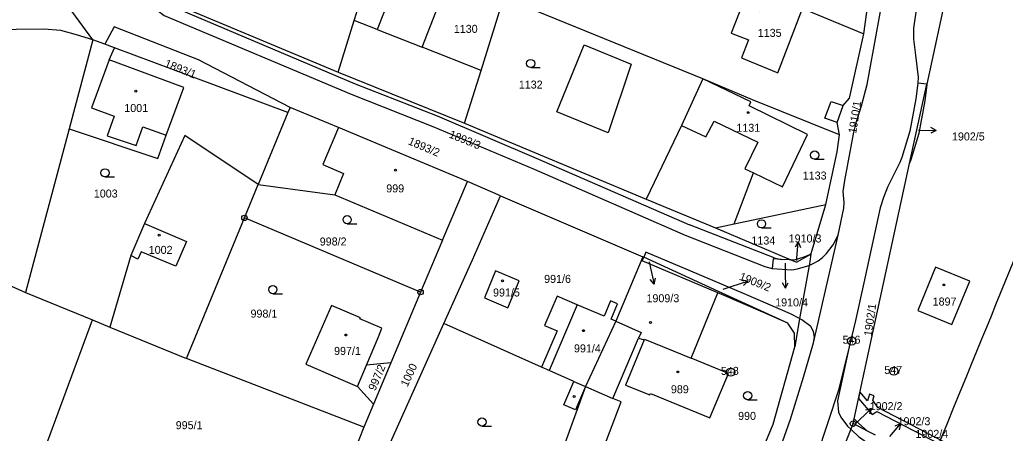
# Model space of a CAD drawing. Extents: x -587171 to -555306, y -1167727 to -1074732.
# Drawn here: x -560044.2 to -559864.5, y -1077385.1 to -1077309.7 of the extents above; entities that cross this region are included whole.
import ezdxf

# ---------------------------------------------------------------- set-up
doc = ezdxf.new("R2010")
doc.units = 0
for name, color, linetype in [('Hranice parcel', 7, 'Continuous'), ('Parcelní čísla', 7, 'Continuous'), ('Pop  PČ popisy', 7, 'Continuous'), ('Poz předměty', 7, 'Continuous'), ('Vnitřní kresba', 7, 'Continuous'), ('Věcná břemena k části', 7, 'Continuous'), ('Značky bodu BP', 7, 'Continuous'), ('Značky budov', 7, 'Continuous'), ('Značky kultur', 7, 'Continuous')]:
    doc.layers.add(name, color=color, linetype=linetype)

msp = doc.modelspace()

# ---------------------------------------------------------------- linework, layer by layer
at = {"layer": 'Hranice parcel'}
for p, q in [((-559983.17, -1077309.84), (-559978.88, -1077295.93)), ((-559890.24, -1077312.26), (-559889.22, -1077304.66)), ((-559875.1, -1077304.36), (-559878.81, -1077321.46)), ((-560030.81, -1077313.36), (-560036.87, -1077305.12)), ((-560016.82, -1077306.44), (-559986.08, -1077319.26)), ((-559960.06, -1077318.93), (-559955.87, -1077305.57)), ((-559919.63, -1077320.49), (-559953.55, -1077306.68)), ((-559986.08, -1077319.26), (-559983.17, -1077309.84)), ((-560030.81, -1077313.36), (-560035.15, -1077329.59)), ((-560028.64, -1077314.17), (-560030.81, -1077313.36)), ((-560026.89, -1077314.82), (-560028.64, -1077314.17)), ((-559963.08, -1077328.55), (-559960.06, -1077318.93)), ((-559986.08, -1077319.26), (-559963.08, -1077328.55)), ((-559881.94, -1077335.91), (-559878.81, -1077321.46)), ((-559994.88, -1077325.68), (-559995.29, -1077326.62)), ((-559995.29, -1077326.62), (-560000.68, -1077339.72)), ((-560035.15, -1077329.59), (-560043.13, -1077359.42)), ((-559963.08, -1077328.55), (-559929.98, -1077342.38)), ((-559892.03, -1077382.43), (-559881.94, -1077335.91)), ((-560003.19, -1077345.82), (-560000.68, -1077339.72)), ((-559967.11, -1077349.89), (-559962.53, -1077339.19)), ((-559956.53, -1077341.81), (-559962.53, -1077339.19)), ((-559956.53, -1077341.81), (-559930.55, -1077352.91)), ((-559929.98, -1077342.38), (-559917.34, -1077347.66)), ((-559913.91, -1077346.93), (-559897.19, -1077343.37)), ((-559899.86, -1077352.3), (-559897.19, -1077343.37)), ((-560013.73, -1077371.45), (-560003.19, -1077345.82)), ((-559971.08, -1077359.35), (-560003.19, -1077345.82)), ((-559917.34, -1077347.66), (-559913.91, -1077346.93)), ((-559917.34, -1077347.66), (-559903.58, -1077353.47)), ((-560062.31, -1077350.83), (-560043.13, -1077359.42)), ((-559967.11, -1077349.89), (-559971.08, -1077359.35)), ((-559930.55, -1077352.91), (-559935.49, -1077364.62)), ((-559930.38, -1077352.99), (-559930.55, -1077352.91)), ((-559899.9, -1077352.45), (-559899.86, -1077352.3)), ((-560043.13, -1077359.42), (-560030.92, -1077364.43)), ((-559971.08, -1077359.35), (-559976.49, -1077372.24)), ((-560030.92, -1077364.43), (-560027.75, -1077365.72)), ((-560027.75, -1077365.72), (-560013.73, -1077371.45)), ((-559978.26, -1077390.49), (-559966.82, -1077365.06)), ((-559949.05, -1077373.02), (-559966.82, -1077365.06)), ((-559935.49, -1077364.62), (-559940.99, -1077376.58)), ((-559901.97, -1077364.19), (-559902.87, -1077369.32)), ((-559981.41, -1077383.96), (-560013.73, -1077371.45)), ((-559982.56, -1077376.53), (-559980.95, -1077372.68)), ((-559976.49, -1077372.24), (-559980.95, -1077372.68)), ((-559976.49, -1077372.24), (-559979.66, -1077379.8)), ((-559982.56, -1077376.53), (-559979.66, -1077379.8)), ((-559940.99, -1077376.58), (-559945, -1077387.63)), ((-559979.66, -1077379.8), (-559981.41, -1077383.96)), ((-559892.23, -1077383.33), (-559892.63, -1077384.34)), ((-559892.23, -1077383.33), (-559892.03, -1077382.43)), ((-559889.58, -1077384.72), (-559892.23, -1077383.33)), ((-559892.63, -1077384.34), (-559894.93, -1077390.1)), ((-559888.16, -1077385.46), (-559889.58, -1077384.72))]:
    msp.add_line(p, q, dxfattribs=at)
for points in [[(-559929.49, -1077288.89), (-559929.57, -1077289.19), (-559932.51, -1077296.57), (-559925.45, -1077299.01), (-559908.07, -1077305.03), (-559909.31, -1077308.22), (-559912.46, -1077307.06), (-559914.44, -1077312.13), (-559911.3, -1077313.35), (-559912.58, -1077316.63), (-559905.97, -1077319.36), (-559901.46, -1077307.62), (-559890.24, -1077312.26)], [(-559900.26, -1077354.47), (-559899.5, -1077354.14), (-559898.62, -1077353.63), (-559897.81, -1077353.03), (-559897.09, -1077352.34), (-559895.86, -1077350.73), (-559894.96, -1077348.94), (-559893.9, -1077344.02), (-559893.86, -1077343.01), (-559894.02, -1077341), (-559893.76, -1077339.02), (-559892.08, -1077330.19), (-559891.58, -1077328.25), (-559890.72, -1077325.37), (-559889.66, -1077321.48), (-559885.92, -1077300.78), (-559885.95, -1077299.24), (-559886.26, -1077298.26), (-559886.87, -1077296.86), (-559887.03, -1077296.56)], [(-559960.06, -1077318.93), (-559970.81, -1077314.7), (-559966.79, -1077304.34), (-559974.94, -1077301.15), (-559979, -1077311.48), (-559983.17, -1077309.84)], [(-560019.97, -1077306.15), (-560019.65, -1077307.12), (-560019.09, -1077307.96), (-560017.85, -1077308.9), (-559983.72, -1077323.25), (-559968.84, -1077329.13), (-559950.38, -1077336.96), (-559922.87, -1077348.95), (-559908.29, -1077354.69), (-559906.95, -1077355.04)], [(-560030.81, -1077313.36), (-560033.78, -1077312.44), (-560036.69, -1077311.68), (-560039.79, -1077311.41), (-560054.98, -1077311.59), (-560063.88, -1077312.39), (-560075.71, -1077315.12), (-560089.9, -1077319.46), (-560101.1, -1077323.43), (-560106.22, -1077325.48)], [(-559994.88, -1077325.68), (-560011.55, -1077317.03), (-560026.95, -1077310.97), (-560028.64, -1077314.17)], [(-559894.71, -1077330.66), (-559895.15, -1077328.43), (-559897.37, -1077327.64), (-559896.22, -1077324.58), (-559894.05, -1077325.32), (-559892.91, -1077324.01), (-559890.24, -1077312.26)], [(-560035.15, -1077329.59), (-560019.01, -1077334.99), (-560017.48, -1077330.74), (-560014.22, -1077322.02), (-560027.88, -1077316.99), (-560026.89, -1077314.82)], [(-559995.29, -1077326.62), (-560012.52, -1077320.18), (-560026.89, -1077314.82)], [(-559919.63, -1077320.49), (-559923.5, -1077328.97), (-559929.98, -1077342.38)], [(-559913.91, -1077346.93), (-559910.4, -1077337.62), (-559905.12, -1077340.17), (-559900.54, -1077330.62), (-559911.16, -1077325.4), (-559910.86, -1077324.65), (-559919.63, -1077320.49)], [(-559894.71, -1077330.66), (-559910.59, -1077324.3), (-559919.63, -1077320.49)], [(-559878.81, -1077321.46), (-559880.41, -1077321.24), (-559880.81, -1077324.13), (-559881.87, -1077330.03), (-559883.35, -1077334.81), (-559883.72, -1077335.71), (-559885.98, -1077340.19), (-559886.66, -1077342.07), (-559887.27, -1077343.97), (-559887.72, -1077345.91), (-559890.29, -1077357.68), (-559891.79, -1077364.53), (-559892.97, -1077369.35), (-559895.09, -1077379.19), (-559894.88, -1077381.21), (-559894.49, -1077382.17), (-559893.24, -1077383.78), (-559892.63, -1077384.34)], [(-559881.94, -1077335.91), (-559881.62, -1077335.17), (-559880.15, -1077330.37), (-559879.08, -1077324.46), (-559878.69, -1077321.48), (-559878.81, -1077321.46)], [(-559962.53, -1077339.19), (-559986.03, -1077329.34), (-559994.88, -1077325.68)], [(-560000.68, -1077339.72), (-560014.03, -1077330.81), (-560021.39, -1077346.86), (-560023.92, -1077352.7), (-560027.75, -1077365.72)], [(-559897.19, -1077343.37), (-559895.13, -1077333.76), (-559894.71, -1077330.66)], [(-560000.68, -1077339.72), (-559986.71, -1077341.63), (-559967.11, -1077349.89)], [(-559966.82, -1077365.06), (-559961.61, -1077353.47), (-559956.53, -1077341.81)], [(-559916.86, -1077359.51), (-559930.65, -1077353.66), (-559930.38, -1077352.99)], [(-559901.97, -1077364.19), (-559903.62, -1077363.31), (-559911.75, -1077359.79), (-559922.24, -1077355.32), (-559930, -1077352.07), (-559930.38, -1077352.99)], [(-559904.13, -1077365.04), (-559916.75, -1077359.25), (-559930.38, -1077352.99)], [(-559903.58, -1077353.47), (-559903.79, -1077353.49), (-559905.36, -1077353.4), (-559906.77, -1077353.31), (-559906.95, -1077355.04)], [(-559903.58, -1077353.47), (-559902.75, -1077353.41), (-559901.13, -1077352.94), (-559900.13, -1077352.48), (-559899.86, -1077352.3)], [(-559903.58, -1077353.47), (-559902.55, -1077353.91), (-559899.9, -1077352.45)], [(-559899.9, -1077352.45), (-559900.13, -1077353.75), (-559900.26, -1077354.47)], [(-559906.95, -1077355.04), (-559903.38, -1077355.27), (-559902.39, -1077355.13), (-559900.45, -1077354.55), (-559900.26, -1077354.47)], [(-559900.26, -1077354.47), (-559901.91, -1077363.84), (-559901.97, -1077364.19)], [(-559880.42, -1077362.71), (-559874.2, -1077365.28), (-559870.95, -1077357.34), (-559877.18, -1077354.78), (-559880.42, -1077362.71)], [(-559957.42, -1077355.46), (-559959.4, -1077360.41), (-559955.16, -1077362.19), (-559953.13, -1077357.3), (-559957.42, -1077355.46)], [(-559935.49, -1077364.62), (-559936.33, -1077364.29), (-559935.17, -1077361.46), (-559936.44, -1077360.95), (-559937.62, -1077363.73), (-559942.51, -1077361.67), (-559946.2, -1077360.09), (-559948.5, -1077365.42), (-559946.16, -1077366.39), (-559949.05, -1077373.02)], [(-559938.79, -1077390.54), (-559934.48, -1077379.33), (-559936.02, -1077378.76), (-559931.32, -1077367.72), (-559930.32, -1077368.08), (-559933.69, -1077376.29), (-559929.26, -1077378.1), (-559929.16, -1077377.85), (-559918.33, -1077382.29), (-559914.91, -1077374.17), (-559921.77, -1077371.37), (-559916.86, -1077359.51)], [(-559904.13, -1077365.04), (-559908.67, -1077362.99), (-559916.18, -1077359.8), (-559916.86, -1077359.51)], [(-559980.95, -1077372.68), (-559978.78, -1077367.5), (-559978.15, -1077365.93), (-559982.13, -1077364.22), (-559982.05, -1077364.03), (-559987.3, -1077361.8), (-559991.97, -1077372.48), (-559982.56, -1077376.53)], [(-560031.56, -1077394.23), (-560040.52, -1077390.39), (-560030.92, -1077364.43)], [(-559905.44, -1077387.67), (-559903.62, -1077382.49), (-559901.27, -1077374.84), (-559899.42, -1077368.57), (-559899.24, -1077367.56), (-559899.43, -1077366.53), (-559899.95, -1077365.64), (-559901.59, -1077364.39), (-559901.97, -1077364.19)], [(-559902.87, -1077369.32), (-559902.91, -1077366.86), (-559904.13, -1077365.04)], [(-559915.17, -1077401.61), (-559908.11, -1077386.67), (-559906.8, -1077383.45), (-559902.87, -1077369.32)], [(-559940.99, -1077376.58), (-559942.83, -1077380.79), (-559944.97, -1077379.88), (-559943.15, -1077375.63), (-559947.66, -1077373.64), (-559949.05, -1077373.02)], [(-559889.58, -1077384.72), (-559891.2, -1077383.33), (-559892.03, -1077382.43)], [(-559981.41, -1077383.96), (-559985.09, -1077393.19), (-559990.04, -1077404.64)], [(-559881.9, -1077390.3), (-559890.22, -1077386.44), (-559891.04, -1077385.83), (-559892.63, -1077384.34)]]:
    msp.add_lwpolyline(points, dxfattribs=at)
at = {"layer": 'Pop  PČ popisy'}
for p, q in [((-559880.33, -1077329.8), (-559880.06, -1077329.81)), ((-559880.06, -1077329.81), (-559877.06, -1077329.86)), ((-559877.06, -1077329.86), (-559878.07, -1077330.35)), ((-559877.06, -1077329.86), (-559878.05, -1077329.34)), ((-559902.22, -1077350.19), (-559902.81, -1077351.14)), ((-559902.48, -1077353.18), (-559902.22, -1077350.19)), ((-559902.22, -1077350.19), (-559901.81, -1077351.23)), ((-559902.51, -1077353.6), (-559902.48, -1077353.18)), ((-559929.41, -1077353.86), (-559929.16, -1077354.99)), ((-559929.16, -1077354.99), (-559928.48, -1077357.91)), ((-559904.63, -1077354.08), (-559904.6, -1077355.65)), ((-559928.48, -1077357.91), (-559928.22, -1077356.83)), ((-559904.6, -1077355.65), (-559904.55, -1077358.65)), ((-559928.48, -1077357.91), (-559929.2, -1077357.05)), ((-559915.9, -1077358.82), (-559914.25, -1077358.28)), ((-559914.25, -1077358.28), (-559911.4, -1077357.35)), ((-559911.4, -1077357.35), (-559912.5, -1077357.19)), ((-559911.4, -1077357.35), (-559912.19, -1077358.14)), ((-559904.55, -1077358.65), (-559905.07, -1077357.66)), ((-559904.55, -1077358.65), (-559904.06, -1077357.64)), ((-559891.05, -1077382.64), (-559888.89, -1077380.55)), ((-559888.89, -1077380.55), (-559889.96, -1077380.89)), ((-559888.89, -1077380.55), (-559889.26, -1077381.61)), ((-559891.76, -1077383.33), (-559891.05, -1077382.64)), ((-559885.5, -1077385.66), (-559883.57, -1077383.36)), ((-559883.57, -1077383.36), (-559884.6, -1077383.81)), ((-559883.57, -1077383.36), (-559883.83, -1077384.45))]:
    msp.add_line(p, q, dxfattribs=at)
at = {"layer": 'Poz předměty'}
msp.add_line((-559845.74, -1077311.35), (-559865.41, -1077359.61), dxfattribs=at)
msp.add_lwpolyline([(-559865.41, -1077359.61), (-559866.24, -1077361.64), (-559867.08, -1077363.71), (-559867.93, -1077365.8), (-559868.81, -1077367.95), (-559869.73, -1077370.2), (-559870.69, -1077372.54), (-559871.69, -1077374.99), (-559872.76, -1077377.62), (-559873.89, -1077380.39), (-559875.09, -1077383.33), (-559876.4, -1077386.52)], dxfattribs=at)
at = {"layer": 'Vnitřní kresba'}
for p, q in [((-560016.75, -1077307.12), (-559983, -1077321.36)), ((-559979, -1077311.48), (-559970.81, -1077314.7)), ((-559946.24, -1077326.5), (-559941.26, -1077314.28)), ((-559941.26, -1077314.28), (-559932.67, -1077317.79)), ((-560027.88, -1077316.99), (-560031.1, -1077325.74)), ((-559932.67, -1077317.79), (-559936.89, -1077330.3)), ((-559880.39, -1077320.16), (-559880.41, -1077321.24)), ((-559983, -1077321.36), (-559968.06, -1077327.24)), ((-560031.1, -1077325.74), (-560026.95, -1077327.27)), ((-559895.15, -1077328.43), (-559894.05, -1077325.32)), ((-560026.95, -1077327.27), (-560028.23, -1077330.85)), ((-559968.06, -1077327.24), (-559949.59, -1077335.09)), ((-559936.89, -1077330.3), (-559946.24, -1077326.5)), ((-559919.06, -1077331.06), (-559917.58, -1077328.17)), ((-559917.58, -1077328.17), (-559909.58, -1077332.03)), ((-560022.94, -1077332.61), (-560021.7, -1077329.19)), ((-560021.7, -1077329.19), (-560017.48, -1077330.74)), ((-559986.03, -1077329.34), (-559988.89, -1077336.1)), ((-559923.5, -1077328.97), (-559919.06, -1077331.06)), ((-560028.23, -1077330.85), (-560022.94, -1077332.61)), ((-559909.58, -1077332.03), (-559911.94, -1077336.89)), ((-559949.59, -1077335.09), (-559922.08, -1077347.06)), ((-559988.89, -1077336.1), (-559985.11, -1077337.7)), ((-559911.94, -1077336.89), (-559910.4, -1077337.62)), ((-559985.11, -1077337.7), (-559986.71, -1077341.63)), ((-560021.39, -1077346.86), (-560013.77, -1077350.11)), ((-559906.59, -1077353.11), (-559922.08, -1077347.06)), ((-559899.42, -1077368.57), (-559894.96, -1077348.94)), ((-560013.77, -1077350.11), (-560015.68, -1077354.61)), ((-560022.61, -1077353.32), (-560023.92, -1077352.7)), ((-560021.99, -1077352.01), (-560022.61, -1077353.32)), ((-560015.68, -1077354.61), (-560021.99, -1077352.01)), ((-559906.59, -1077353.11), (-559905.36, -1077353.4)), ((-559942.51, -1077361.67), (-559947.66, -1077373.64)), ((-559935.49, -1077364.62), (-559930.89, -1077366.72)), ((-559930.89, -1077366.72), (-559931.32, -1077367.72)), ((-559930.32, -1077368.08), (-559930.25, -1077367.91)), ((-559930.25, -1077367.91), (-559921.77, -1077371.37)), ((-559892.97, -1077369.35), (-559894.9, -1077377.22)), ((-559943.15, -1077375.63), (-559940.99, -1077376.58)), ((-559940.99, -1077376.58), (-559936.02, -1077378.76)), ((-559894.9, -1077377.22), (-559899.37, -1077390.82))]:
    msp.add_line(p, q, dxfattribs=at)
msp.add_lwpolyline([(-559880.52, -1077306.69), (-559881.2, -1077311.2), (-559881.19, -1077313.22), (-559880.84, -1077316.18), (-559880.39, -1077320.16)], dxfattribs=at)
at = {"layer": 'Věcná břemena k části'}
msp.add_lwpolyline([(-559859.52, -1077396.96), (-559855.23, -1077398.97), (-559856.09, -1077398.29), (-559860.3, -1077395.64), (-559866.99, -1077392.11), (-559869.5, -1077390.07), (-559871.22, -1077389.29), (-559872.65, -1077388.25), (-559887.7, -1077380.39), (-559888.62, -1077379.05), (-559888.38, -1077378.28), (-559889.22, -1077377.97), (-559889.59, -1077379.15), (-559890.97, -1077377.54), (-559891.24, -1077378.77), (-559888.75, -1077381.66), (-559887.87, -1077381.09), (-559873.01, -1077388.85), (-559871.58, -1077389.89), (-559869.88, -1077390.67), (-559867.37, -1077392.69), (-559860.66, -1077396.24)], close=True, dxfattribs=at)
at = {"layer": 'Značky bodu BP'}
for centre, radius in [((-560003.19, -1077345.82), 0.5), ((-560003.19, -1077345.82), 0.0303), ((-559971.08, -1077359.35), 0.5), ((-559971.08, -1077359.35), 0.0303), ((-559892.47, -1077368.26), 0.75), ((-559892.47, -1077368.26), 0.03), ((-559884.8, -1077373.77), 0.75), ((-559914.55, -1077373.94), 0.75), ((-559914.55, -1077373.94), 0.03), ((-559884.8, -1077373.77), 0.03), ((-559892.23, -1077383.33), 0.5), ((-559892.23, -1077383.33), 0.0303)]:
    msp.add_circle(centre, radius, dxfattribs=at)
at = {"layer": 'Značky budov'}
for centre in [(-560022.98, -1077322.72), (-559911.33, -1077326.63), (-559975.64, -1077337.11), (-560018.76, -1077348.96), (-559956.13, -1077357.3), (-559875.69, -1077358.05), (-559929.17, -1077364.87), (-559984.69, -1077367.17), (-559941.39, -1077366.38), (-559924.2, -1077373.91), (-559943.1, -1077378.36)]:
    msp.add_circle(centre, 0.175, dxfattribs=at)
at = {"layer": 'Značky kultur'}
for p, q in [((-559951, -1077318.42), (-559949.25, -1077318.42)), ((-559899.24, -1077335.12), (-559897.49, -1077335.12)), ((-560028.63, -1077338.36), (-560026.88, -1077338.36)), ((-559984.46, -1077346.9), (-559982.71, -1077346.9)), ((-559908.93, -1077347.65), (-559907.18, -1077347.65)), ((-559998.01, -1077359.64), (-559996.26, -1077359.64)), ((-559911.45, -1077378.97), (-559909.7, -1077378.97)), ((-559959.89, -1077383.79), (-559958.14, -1077383.79))]:
    msp.add_line(p, q, dxfattribs=at)
for centre in [(-559951, -1077317.67), (-559899.24, -1077334.37), (-560028.63, -1077337.61), (-559984.46, -1077346.15), (-559908.93, -1077346.9), (-559998.01, -1077358.89), (-559911.45, -1077378.22), (-559959.89, -1077383.04)]:
    msp.add_circle(centre, 0.75, dxfattribs=at)

# ---------------------------------------------------------------- texts
at = {"layer": 'Parcelní čísla'}
for s, p in [('1130', (-559965.02, -1077312.08)), ('1135', (-559909.6, -1077312.81)), ('1132', (-559953.17, -1077322.24)), ('1001', (-560025.09, -1077326.51)), ('1131', (-559913.5, -1077330.12)), ('1902/5', (-559874.2, -1077331.7)), ('1133', (-559901.4, -1077338.83)), ('1003', (-560030.65, -1077342.11)), ('999', (-559977.33, -1077341.17)), ('998/2', (-559989.46, -1077350.85)), ('1134', (-559910.76, -1077350.67)), ('1910/3', (-559903.97, -1077350.3)), ('1002', (-560020.64, -1077352.38)), ('991/6', (-559948.55, -1077357.67)), ('991/5', (-559957.87, -1077360.15)), ('1909/3', (-559929.89, -1077361.2)), ('1910/4', (-559906.43, -1077361.95)), ('1897', (-559877.72, -1077361.8)), ('998/1', (-560002.08, -1077364)), ('997/1', (-559986.85, -1077370.8)), ('991/4', (-559943.11, -1077370.34)), ('989', (-559925.44, -1077377.79)), ('1902/2', (-559889.19, -1077380.87)), ('990', (-559913.19, -1077382.65)), ('1902/3', (-559884.11, -1077383.62)), ('995/1', (-560015.72, -1077384.34)), ('1902/4', (-559880.86, -1077385.92))]:
    msp.add_text(s, height=1.46, dxfattribs=at).set_placement(p)
for s, rotation, p in [('1893/1', 338, (-560017.88, -1077318.2)), ('1910/1', 81, (-559891.67, -1077330.5)), ('1893/3', 338, (-559966.02, -1077331.13)), ('1893/2', 337, (-559973.47, -1077332.36)), ('1909/2', 338, (-559913.11, -1077357.05)), ('1902/1', 82, (-559888.83, -1077367.47)), ('997/2', 67, (-559979.34, -1077377.45)), ('1000', 65, (-559973.47, -1077376.73))]:
    msp.add_text(s, height=1.46, rotation=rotation, dxfattribs=at).set_placement(p)
at = {"layer": 'Značky bodu BP'}
for s, p in [('546', (-559894.14, -1077368.76)), ('548', (-559916.32, -1077374.44)), ('547', (-559886.53, -1077374.27))]:
    msp.add_text(s, height=1.46, dxfattribs=at).set_placement(p)

doc.saveas('drawing.dxf')
